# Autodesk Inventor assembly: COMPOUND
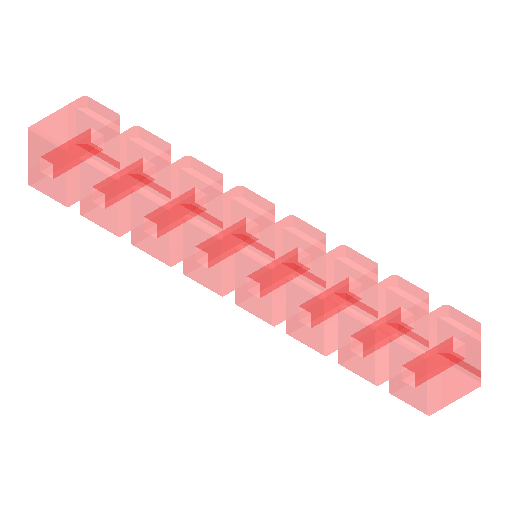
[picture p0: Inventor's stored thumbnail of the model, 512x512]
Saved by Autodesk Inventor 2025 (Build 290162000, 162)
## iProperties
Created: 2025-05
Part Number: COMPOUND
Document SubType Name: Assembly
Designer: R5800u
Author: R5800u
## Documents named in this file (9)
- C:\Users\R5800u\Desktop\drone\c3\ESP32-C3 Super Mini breakout expansion board module -Assembly\COMPOUND_3.iam
- C:\Users\R5800u\Desktop\drone\c3\ESP32-C3 Super Mini breakout expansion board module -Assembly\COMPOUND_24.ipt
- C:\Users\R5800u\Desktop\drone\c3\ESP32-C3 Super Mini breakout expansion board module -Assembly\COMPOUND_25.ipt
- C:\Users\R5800u\Desktop\drone\c3\ESP32-C3 Super Mini breakout expansion board module -Assembly\COMPOUND_26.ipt
- C:\Users\R5800u\Desktop\drone\c3\ESP32-C3 Super Mini breakout expansion board module -Assembly\COMPOUND_27.ipt
- C:\Users\R5800u\Desktop\drone\c3\ESP32-C3 Super Mini breakout expansion board module -Assembly\COMPOUND_28.ipt
- C:\Users\R5800u\Desktop\drone\c3\ESP32-C3 Super Mini breakout expansion board module -Assembly\COMPOUND_29.ipt
- C:\Users\R5800u\Desktop\drone\c3\ESP32-C3 Super Mini breakout expansion board module -Assembly\COMPOUND_30.ipt
- C:\Users\R5800u\Desktop\drone\c3\ESP32-C3 Super Mini breakout expansion board module -Assembly\COMPOUND_31.ipt
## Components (8 placed, 8 different names)
1. 30
2. 31
3. 32
4. 33
5. 34
6. 35
7. 36
8. 37
